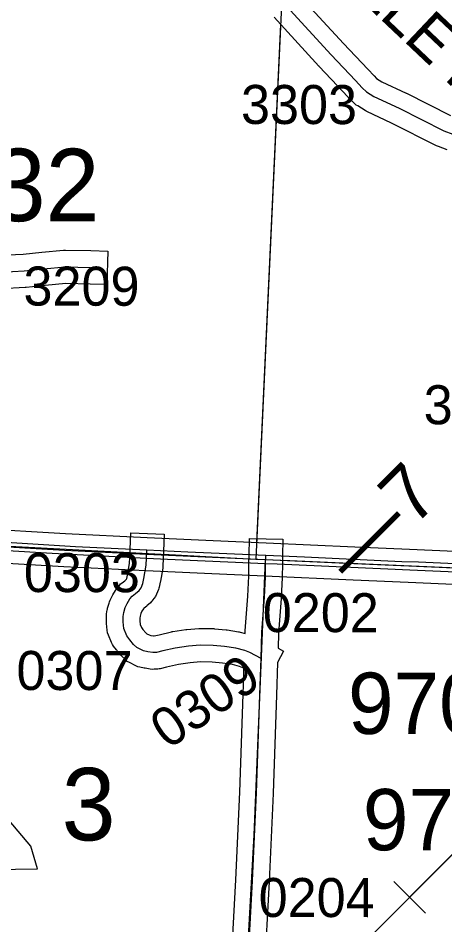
# Model space of a CAD drawing. Extents: x -157.2 to -99.3, y 12.2 to 46.2.
# Drawn here: x -143.029 to -142.263, y 34.467 to 36.094 of the extents above; entities that cross this region are included whole.
import ezdxf

# ---------------------------------------------------------------- set-up
doc = ezdxf.new("R2010")
doc.units = 0
for name, color, linetype in [('tdCoCorpBndry', 7, 'Continuous'), ('tdCoDivCarto', 7, 'Continuous'), ('tdCoPipe', 7, 'Continuous'), ('tdCoPriCL', 7, 'Continuous'), ('tdCoPriDiv', 7, 'Continuous'), ('tdCoSecRdNmbr', 7, 'Continuous'), ('tdCoSecRdTxt', 7, 'Continuous'), ('tdCoSecRteBand', 7, 'Continuous'), ('tdCoSecRteCL', 7, 'Continuous'), ('tdCoSectLine', 7, 'Continuous'), ('tdCoSectLinePart', 7, 'Continuous'), ('tdCoSectNmbr', 7, 'Continuous'), ('tdCoStrucPriMaintName', 7, 'Continuous'), ('tdCoSurfAsphalt', 7, 'Continuous'), ('tdCoSurfConc', 7, 'Continuous'), ('tdCoSurfGravel', 7, 'Continuous'), ('tdCoTwpBndryShd', 7, 'Continuous'), ('tdStHwyPriRefPost1', 7, 'Continuous')]:
    doc.layers.add(name, color=color, linetype=linetype)

msp = doc.modelspace()

# ---------------------------------------------------------------- linework, layer by layer
at = {"layer": 'tdCoCorpBndry'}
msp.add_lwpolyline([(-143.1379, 34.0664), (-143.1135, 34.5657), (-142.9939, 34.5674), (-143.0062, 34.6084), (-143.0453, 34.6543), (-143.0605, 34.6717), (-143.0879, 34.7703), (-143.1122, 34.815), (-143.4474, 34.8111), (-143.4293, 35.1402), (-143.52, 35.1438), (-143.5239, 35.0781), (-143.5764, 35.0798), (-143.608, 34.5592), (-144.1211, 34.5524), (-144.2859, 34.5502), (-144.3565, 34.3415)], dxfattribs=at)
at = {"layer": 'tdCoDivCarto'}
for points in [[(-140.6246, 35.0501), (-140.8384, 35.0567), (-141.0399, 35.0641), (-141.2426, 35.0715), (-141.4288, 35.0787), (-141.5838, 35.0857), (-141.6137, 35.0871), (-141.8223, 35.0972), (-142.01, 35.104), (-142.0132, 35.1041), (-142.0336, 35.105), (-142.1024, 35.108), (-142.1868, 35.1117), (-142.2184, 35.1135), (-142.3106, 35.1176), (-142.3402, 35.1186), (-142.5151, 35.1267), (-142.5844, 35.1296), (-142.7242, 35.1356), (-142.7979, 35.1392), (-142.9262, 35.1454), (-143.0988, 35.1558)], [(-140.6246, 35.0501), (-140.8384, 35.0567), (-141.0399, 35.0641), (-141.2426, 35.0715), (-141.4288, 35.0787), (-141.5838, 35.0857), (-141.6137, 35.0871), (-141.8223, 35.0972), (-142.01, 35.104), (-142.0132, 35.1041), (-142.0336, 35.105), (-142.1024, 35.108), (-142.1868, 35.1117), (-142.2184, 35.1135), (-142.3106, 35.1176), (-142.3402, 35.1186), (-142.5151, 35.1267), (-142.5844, 35.1296), (-142.7242, 35.1356), (-142.7979, 35.1392), (-142.9262, 35.1454), (-143.0988, 35.1558)], [(-143.148, 35.1444), (-142.968, 35.1338), (-142.7985, 35.1251), (-142.7609, 35.1232), (-142.5847, 35.1154), (-142.5641, 35.1145), (-142.3256, 35.1039), (-142.1741, 35.0975), (-142.1031, 35.0946), (-142.0431, 35.0921), (-142.0179, 35.091), (-141.9744, 35.0892), (-141.8407, 35.083), (-141.732, 35.0783), (-141.5849, 35.0715), (-141.5401, 35.0694), (-141.423, 35.0647), (-141.3263, 35.0606), (-141.1174, 35.0517), (-140.9448, 35.0463), (-140.734, 35.0393)], [(-143.148, 35.1444), (-142.968, 35.1338), (-142.7985, 35.1251), (-142.7609, 35.1232), (-142.5847, 35.1154), (-142.5641, 35.1145), (-142.3256, 35.1039), (-142.1741, 35.0975), (-142.1031, 35.0946), (-142.0431, 35.0921), (-142.0179, 35.091), (-141.9744, 35.0892), (-141.8407, 35.083), (-141.732, 35.0783), (-141.5849, 35.0715), (-141.5401, 35.0694), (-141.423, 35.0647), (-141.3263, 35.0606), (-141.1174, 35.0517), (-140.9448, 35.0463), (-140.734, 35.0393)]]:
    msp.add_lwpolyline(points, dxfattribs=at)
at = {"layer": 'tdCoPipe'}
msp.add_line((-142.2978, 34.4879), (-142.3547, 34.5448), dxfattribs=at)
for points in [[(-145.5545, 32.0407), (-145.4652, 31.9559), (-145.2641, 32.039), (-144.2371, 32.0131), (-143.232, 33.3859), (-142.9301, 33.9124), (-142.0867, 34.756), (-141.6374, 35.6825), (-141.5355, 35.8566), (-140.3685, 37.1582), (-139.4239, 38.0364), (-138.0693, 39.5013), (-138.0266, 39.825), (-137.4064, 40.3449), (-136.8596, 41.0707)], [(-142.3263, 34.5164), (-142.1135, 34.7293)]]:
    msp.add_lwpolyline(points, dxfattribs=at)
at = {"layer": 'tdCoPriCL'}
msp.add_lwpolyline([(-143.1084, 35.1491), (-142.9455, 35.1393), (-142.7986, 35.1319), (-142.6802, 35.1267), (-142.5849, 35.1225), (-142.4262, 35.1155), (-142.3275, 35.111), (-142.1789, 35.1047)], dxfattribs=at)
at = {"layer": 'tdCoPriDiv'}
for points in [[(-143.1066, 35.179), (-142.9439, 35.1693), (-142.7972, 35.1619), (-142.6789, 35.1567), (-142.5836, 35.1525), (-142.4248, 35.1455), (-142.3262, 35.1409), (-142.1775, 35.1346), (-142.1018, 35.1308), (-142.0776, 35.1298), (-142.0583, 35.1292), (-142.032, 35.1282), (-142.0203, 35.1277), (-141.9769, 35.126), (-141.8276, 35.1198), (-141.614, 35.1104), (-141.4252, 35.1015), (-141.177, 35.091), (-140.8292, 35.0788), (-140.5825, 35.0718)], [(-140.5842, 35.0118), (-140.8311, 35.0188), (-141.1793, 35.031), (-141.4278, 35.0415), (-141.6168, 35.0505), (-141.8302, 35.0599), (-141.9793, 35.066), (-142.0188, 35.0676), (-142.0227, 35.0678), (-142.0344, 35.0682), (-142.0604, 35.0693), (-142.0797, 35.0699), (-142.1045, 35.0709), (-142.1803, 35.0747), (-142.3288, 35.081), (-142.4275, 35.0856), (-142.5862, 35.0926), (-142.6815, 35.0967), (-142.8, 35.102), (-142.9472, 35.1093), (-143.1102, 35.1191)]]:
    msp.add_lwpolyline(points, dxfattribs=at)
at = {"layer": 'tdCoSecRteBand'}
for points in [[(-142.5252, 36.1359), (-142.445, 36.0485), (-142.4015, 36.0025), (-142.4013, 36.0024), (-142.4012, 36.0023), (-142.3901, 35.9902), (-142.3855, 35.9859), (-142.3759, 35.98), (-142.3325, 35.9595), (-142.3322, 35.9593), (-142.3318, 35.9591), (-142.2529, 35.9193)], [(-142.2587, 35.8577), (-142.2747, 35.8634), (-142.2765, 35.864), (-142.2782, 35.8649), (-142.3585, 35.9054), (-142.403, 35.9264), (-142.4045, 35.9271), (-142.406, 35.928), (-142.4195, 35.9364), (-142.4221, 35.938), (-142.4243, 35.94), (-142.4319, 35.9472), (-142.4327, 35.9479), (-142.4335, 35.9487), (-142.4452, 35.9614), (-142.4887, 36.0074), (-142.4888, 36.0076), (-142.489, 36.0077), (-142.5696, 36.0955)], [(-143.0606, 35.6684), (-143.0202, 35.6703), (-142.9866, 35.6739), (-142.9864, 35.6739), (-142.9862, 35.674), (-142.9473, 35.6776), (-142.9455, 35.6778), (-142.9438, 35.6778), (-142.8982, 35.6768), (-142.8682, 35.6761), (-142.8695, 35.6162), (-142.8995, 35.6168), (-142.9433, 35.6178), (-142.9804, 35.6142), (-143.0147, 35.6106), (-143.0156, 35.6105), (-143.0165, 35.6104), (-143.0587, 35.6084)], [(-142.6473, 34.382), (-142.6384, 34.5477), (-142.6308, 34.7052), (-142.6252, 34.8808), (-142.6252, 34.8808), (-142.6252, 34.8808), (-142.624, 34.9162), (-142.6236, 34.9271), (-142.6259, 34.9282), (-142.6315, 34.9306), (-142.6442, 34.9339), (-142.6621, 34.9367), (-142.6806, 34.9385), (-142.7014, 34.9387), (-142.72, 34.9372), (-142.7413, 34.934), (-142.7625, 34.9291), (-142.7627, 34.9291), (-142.7628, 34.9291), (-142.7739, 34.9266), (-142.776, 34.9261), (-142.7782, 34.926), (-142.7848, 34.9255), (-142.7884, 34.9252), (-142.7918, 34.9258), (-142.801, 34.9273), (-142.8018, 34.9274), (-142.8026, 34.9276), (-142.8105, 34.9293), (-142.8143, 34.9301), (-142.8177, 34.9319), (-142.8293, 34.9378), (-142.8332, 34.9398), (-142.8364, 34.9429), (-142.8423, 34.9485), (-142.8434, 34.9496), (-142.8444, 34.9508), (-142.8514, 34.9589), (-142.8519, 34.9596), (-142.8525, 34.9603), (-142.8577, 34.9673), (-142.8598, 34.9702), (-142.8613, 34.9735), (-142.8669, 34.9868), (-142.8687, 34.991), (-142.8692, 34.9955), (-142.8704, 35.0076), (-142.8706, 35.0091), (-142.8706, 35.0107), (-142.8706, 35.02), (-142.8706, 35.0226), (-142.8701, 35.0251), (-142.8689, 35.0323), (-142.8687, 35.0337), (-142.8683, 35.035), (-142.8658, 35.0441), (-142.8651, 35.0468), (-142.8639, 35.0494), (-142.8602, 35.057), (-142.8596, 35.0582), (-142.859, 35.0593), (-142.8543, 35.0672), (-142.853, 35.0693), (-142.8513, 35.0713), (-142.8471, 35.0762), (-142.845, 35.0787), (-142.8424, 35.0807), (-142.8374, 35.0845), (-142.8343, 35.0873), (-142.8338, 35.0885), (-142.8325, 35.0943), (-142.829, 35.1154), (-142.8285, 35.1264), (-142.8279, 35.1405), (-142.8265, 35.1705), (-142.7666, 35.1678), (-142.7679, 35.1378), (-142.7686, 35.1238), (-142.7692, 35.1109), (-142.7692, 35.1091), (-142.7695, 35.1073), (-142.7735, 35.0836), (-142.7736, 35.0829), (-142.7738, 35.0821), (-142.7758, 35.0732), (-142.7763, 35.0709), (-142.7771, 35.0687), (-142.7803, 35.0606), (-142.7821, 35.0561), (-142.7852, 35.0524), (-142.7889, 35.0479), (-142.7902, 35.0464), (-142.7916, 35.045), (-142.7978, 35.0394), (-142.7988, 35.0384), (-142.8, 35.0376), (-142.8035, 35.0349), (-142.804, 35.0343), (-142.8067, 35.0297), (-142.8086, 35.0258), (-142.81, 35.0207), (-142.8106, 35.0175), (-142.8106, 35.0122), (-142.8099, 35.0061), (-142.8075, 35.0003), (-142.805, 34.9971), (-142.7997, 34.9908), (-142.7981, 34.9892), (-142.7939, 34.9871), (-142.7906, 34.9864), (-142.7857, 34.9856), (-142.7848, 34.9857), (-142.7759, 34.9876), (-142.7536, 34.9928), (-142.7524, 34.9931), (-142.7512, 34.9932), (-142.7278, 34.9967), (-142.7268, 34.9968), (-142.7259, 34.9969), (-142.7049, 34.9986), (-142.7035, 34.9987), (-142.7021, 34.9987), (-142.6787, 34.9985), (-142.6774, 34.9985), (-142.6762, 34.9983), (-142.6555, 34.9964), (-142.6545, 34.9963), (-142.6536, 34.9961), (-142.6334, 34.9929), (-142.632, 34.9927), (-142.6306, 34.9924), (-142.6216, 34.99), (-142.6215, 34.993), (-142.6214, 34.9937), (-142.6214, 34.9943), (-142.6168, 35.0567), (-142.6151, 35.0924), (-142.6147, 35.116), (-142.6144, 35.1302), (-142.6138, 35.1602), (-142.5538, 35.1591), (-142.5544, 35.1291), (-142.5547, 35.1149), (-142.5551, 35.0909), (-142.5551, 35.0904), (-142.5551, 35.09), (-142.5569, 35.0535), (-142.5569, 35.0531), (-142.5569, 35.0527), (-142.5615, 34.9905), (-142.5624, 34.9633), (-142.5527, 34.9583), (-142.5633, 34.9375), (-142.5652, 34.8789), (-142.5709, 34.7031), (-142.5709, 34.7028), (-142.5709, 34.7026), (-142.5785, 34.5447), (-142.5785, 34.5447), (-142.5785, 34.5446), (-142.5874, 34.3786)]]:
    msp.add_lwpolyline(points, dxfattribs=at)
at = {"layer": 'tdCoSecRteCL'}
for points in [[(-142.5475, 36.1158), (-142.4669, 36.028), (-142.4233, 35.9819), (-142.4114, 35.9691), (-142.4038, 35.9619), (-142.3902, 35.9535), (-142.3453, 35.9323), (-142.2647, 35.8917), (-142.2487, 35.886), (-142.2356, 35.8838), (-142.2235, 35.8835), (-142.1863, 35.8801), (-142.0995, 35.8736), (-142.0754, 35.8715)], [(-143.3251, 35.6573), (-143.3248, 35.6572), (-143.3116, 35.6552), (-143.2823, 35.648), (-143.2598, 35.6433), (-143.2426, 35.6421), (-143.174, 35.6409), (-143.1023, 35.6389), (-143.0601, 35.6384), (-143.0179, 35.6404), (-142.9834, 35.6441), (-142.9444, 35.6478), (-142.8988, 35.6468)], [(-142.593, 34.9452), (-142.6132, 34.9554), (-142.6218, 34.9591), (-142.6381, 34.9633), (-142.6583, 34.9665), (-142.679, 34.9685), (-142.7025, 34.9687), (-142.7234, 34.967), (-142.7468, 34.9636), (-142.7693, 34.9584), (-142.7804, 34.9559), (-142.787, 34.9554), (-142.7962, 34.9569), (-142.8041, 34.9586), (-142.8157, 34.9645), (-142.8216, 34.9702), (-142.8285, 34.9783), (-142.8337, 34.9853), (-142.8393, 34.9986), (-142.8406, 35.0107), (-142.8406, 35.02), (-142.8393, 35.0272), (-142.8369, 35.0363), (-142.8332, 35.0439), (-142.8285, 35.0518), (-142.8243, 35.0568), (-142.8181, 35.0615), (-142.812, 35.0671), (-142.8083, 35.0716), (-142.805, 35.0797), (-142.8031, 35.0886), (-142.7991, 35.1122), (-142.7985, 35.1251), (-142.7979, 35.1392)], [(-142.593, 34.9452), (-142.5915, 34.9921), (-142.5868, 35.0549), (-142.5851, 35.0914), (-142.5847, 35.1154), (-142.5844, 35.1296)], [(-142.6358, 34.0685), (-142.6354, 34.0907), (-142.6287, 34.2032), (-142.6208, 34.3277), (-142.6174, 34.3802), (-142.6085, 34.5462), (-142.6008, 34.704), (-142.5952, 34.8799), (-142.593, 34.9452)]]:
    msp.add_lwpolyline(points, dxfattribs=at)
at = {"layer": 'tdCoSectLine'}
for points in [[(-142.5564, 36.1172), (-142.6022, 35.1233)], [(-143.5717, 35.1631), (-143.3512, 35.1624), (-142.6022, 35.1233)], [(-142.6362, 34.0685), (-142.6051, 34.628), (-142.5849, 35.1225)], [(-142.6022, 35.1233), (-142.5849, 35.1225)], [(-142.5849, 35.1225), (-141.6061, 35.08)]]:
    msp.add_lwpolyline(points, dxfattribs=at)
at = {"layer": 'tdCoSectLinePart'}
for points in [[(-142.558, 36.0825), (-142.6009, 35.1528)], [(-143.3214, 35.1608), (-142.8285, 35.1351)], [(-142.7686, 35.132), (-142.6149, 35.124)], [(-142.5549, 35.1212), (-142.1333, 35.1029)]]:
    msp.add_lwpolyline(points, dxfattribs=at)
at = {"layer": 'tdCoSurfAsphalt'}
msp.add_lwpolyline([(-142.5475, 36.1158), (-142.4669, 36.028), (-142.4233, 35.9819), (-142.4114, 35.9691), (-142.4038, 35.9619), (-142.3902, 35.9535), (-142.3453, 35.9323), (-142.2647, 35.8917), (-142.2487, 35.886), (-142.2356, 35.8838), (-142.2235, 35.8835)], dxfattribs=at)
at = {"layer": 'tdCoSurfConc'}
msp.add_lwpolyline([(-142.593, 34.9452), (-142.6132, 34.9554), (-142.6218, 34.9591), (-142.6381, 34.9633), (-142.6583, 34.9665), (-142.679, 34.9685), (-142.7025, 34.9687), (-142.7234, 34.967), (-142.7468, 34.9636), (-142.7693, 34.9584), (-142.7804, 34.9559), (-142.787, 34.9554), (-142.7962, 34.9569), (-142.8041, 34.9586), (-142.8157, 34.9645), (-142.8216, 34.9702), (-142.8285, 34.9783), (-142.8337, 34.9853), (-142.8393, 34.9986), (-142.8406, 35.0107), (-142.8406, 35.02), (-142.8393, 35.0272), (-142.8369, 35.0363), (-142.8332, 35.0439), (-142.8285, 35.0518), (-142.8243, 35.0568), (-142.8181, 35.0615), (-142.812, 35.0671), (-142.8083, 35.0716), (-142.805, 35.0797), (-142.8031, 35.0886), (-142.7991, 35.1122), (-142.7985, 35.1251), (-142.7979, 35.1392)], dxfattribs=at)
at = {"layer": 'tdCoSurfGravel'}
for points in [[(-143.3248, 35.6572), (-143.3116, 35.6552), (-143.2823, 35.648), (-143.2598, 35.6433), (-143.2426, 35.6421), (-143.174, 35.6409), (-143.1023, 35.6389), (-143.0601, 35.6384), (-143.0179, 35.6404), (-142.9834, 35.6441), (-142.9444, 35.6478), (-142.8988, 35.6468)], [(-142.6174, 34.3802), (-142.6085, 34.5462), (-142.6008, 34.704), (-142.5952, 34.8799), (-142.593, 34.9452), (-142.5915, 34.9921), (-142.5868, 35.0549), (-142.5851, 35.0914), (-142.5847, 35.1154), (-142.5844, 35.1296)]]:
    msp.add_lwpolyline(points, dxfattribs=at)
at = {"layer": 'tdCoTwpBndryShd'}
msp.add_lwpolyline([(-147.4022, 35.3159), (-146.6462, 35.2847), (-146.5219, 35.2777), (-145.6295, 35.2357), (-145.6101, 35.2359), (-144.6409, 35.2095), (-144.5981, 35.2067), (-144.0659, 35.1684), (-143.891, 35.1616), (-143.6103, 35.1628), (-143.5717, 35.1631), (-143.3512, 35.1624), (-142.6022, 35.1233), (-142.5849, 35.1225), (-141.6061, 35.08), (-141.5855, 35.079), (-140.6073, 35.0425)], dxfattribs=at)

# ---------------------------------------------------------------- texts
at = {"layer": 'tdCoSecRdNmbr'}
for s, rotation, p in [('3303', 359.8912, (-142.629, 35.9042)), ('3209', 359.8909, (-143.0194, 35.5783)), ('3304', 359.8914, (-142.3011, 35.3653)), ('0303', 359.891, (-143.0187, 35.0642)), ('0202', 359.8912, (-142.5899, 34.9924)), ('0307', 359.891, (-143.032, 34.8885)), ('0309', 34.4964, (-142.76, 34.7806)), ('0204', 359.8912, (-142.5973, 34.4811))]:
    msp.add_text(s, height=0.07, rotation=rotation, dxfattribs=at).set_placement(p)
at = {"layer": 'tdCoSecRdTxt'}
msp.add_text('CORRECTIONVILLE RD', height=0.08, rotation=316.6092, dxfattribs=at).set_placement((-143.0218, 36.7))
at = {"layer": 'tdCoSectNmbr'}
for s, p in [('32', (-143.0764, 35.7298)), ('3', (-142.9509, 34.6186))]:
    msp.add_text(s, height=0.13, rotation=359.8908, dxfattribs=at).set_placement(p)
at = {"layer": 'tdCoStrucPriMaintName'}
for s, p in [('97077L020', (-142.4369, 34.8095)), ('97077R020', (-142.4102, 34.6007))]:
    msp.add_text(s, height=0.11, dxfattribs=at).set_placement(p)
at = {"layer": 'tdStHwyPriRefPost1'}
msp.add_text('‒‒7', height=0.1, rotation=45, dxfattribs=at).set_placement((-142.4245, 35.0745))

doc.saveas('drawing.dxf')
